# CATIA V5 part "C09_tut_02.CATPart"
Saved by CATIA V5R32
Part number: Part1
Bounding box of the stored display mesh (mm): x -258 to 0, y -74.587 to 74.587, z -81.796 to 81.796
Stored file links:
  D:\PROJECTS\Project 2022\CATIA V5 6R 2022\Resources\Tutorial Files\c09_catia_v5_6r2022_tut\C09_tut_02.CATPart
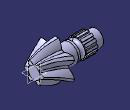
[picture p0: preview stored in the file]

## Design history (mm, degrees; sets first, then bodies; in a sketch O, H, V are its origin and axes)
Body1 (main body)
  Sketch1 on zx-plane, origin (0, 0, 0), H (-1, 0, 0), V (0, 0, 1)
    line L1 (0, 0) -> (258, 0)
    line L2 (258, 0) -> (258, -32.5)
    line L3 (0, 0) -> (0, -25)
    line L4 (0, -25) -> (95, -50)
    point P4 (95, -50)
    point P5 (95, -50)
    line L5 (95, -50) -> (95, -45)
    line L6 (95, -45) -> (100, -45)
    line L7 (100, -45) -> (100, -39)
    line L8 (100, -39) -> (146, -39)
    line L9 (258, -32.5) -> (226, -32.5)
    line L10 (226, -32.5) -> (226, -36)
    line L11 (226, -36) -> (178, -36)
    arc A1 centre (167, -36) radius 11 from (178, -36) to (156, -36) ccw
    point P13 (167, -36)
    line L12 (146, -39) -> (146, -38)
    line L13 (146, -38) -> (156, -38)
    line L14 (156, -38) -> (156, -36)
    point P16 (156, -36)
    point P17 (156, -36)
    axis line L15 (258, 0) -> (-34.5416, 0)
    length L1 = 258
    length L2 = 32.5
    length L3 = 25
    distance P4 L3 = 95
    length L6 = 5
    distance L6 L1 = 45
    length L9 = 32
    radius A1 = 11
    length L13 = 10
    length L14 = 2
    distance L13 L1 = 38
    length L11 = 48
    distance L8 L1 = 39
    distance P4 L1 = 50
    distance L11 L1 = 36
    horizontal: L1 H, L6 H, L8 H, L9 H, L11 H, L13 H, L15 H
    vertical: L2 V, L3 V, L5 V, L7 V, L10 V, L12 V, L14 V
    coincidence: P5 P4, P13 L11, P16 P17
  Shaft1: profile Sketch1, axis Sketch1.L15, angle 360
  Sketch2 on face of Shaft1 from Sketch1.L10, origin (-226, 0, 0), H (0, -1, 0), V (0, 0, 1)
    line L1 (-5, 40.6511) -> (5, 40.6511)
    line L2 (5, 40.6511) -> (5, 35.6511)
    line L3 (-5, 35.6511) -> (-5, 40.6511)
    point P3 (5, 35.6511)
    point P4 (-5, 35.6511)
    reference projected circle E1 centre (0, 0) radius 36 from edge [face of Shaft1 from Sketch1.L10 | face of Shaft1 from Sketch1.L11]
    reference projected circle E2 centre (0, 0) radius 36 from edge [face of Shaft1 from Sketch1.L10 | face of Shaft1 from Sketch1.L11]
    point P5 (0, 35.9986)
    point P6 (12.0414, 33.9264)
    arc A1 centre (0, 0) radius 36 from (5, 35.6511) to (-5, 35.6511) ccw
    length L3 = 5
    length L1 = 10
    distance L2 V = 5
    horizontal: L1 H
    vertical: L2 V, L3 V
    coincidence: P3 E1, P4 E2, P5 V
  Pad1: profile Sketch2, direction (1, 0, 0), length 48
  CircPattern1: of Pad1, instances 13, angular step 27.6923 {= 360.0*1 deg/CircPattern1.AngularNumber}, axis from face of Shaft1 from Sketch1.L9
  Plane1: type Offset, RefPlane face of Shaft1 from Sketch1.L2, Offset 163
  Sketch3 on Plane1, origin (-95, 0, 0), H (0, 1, 0), V (0, 0, 1)
    projected circle E1 centre (0, 0) radius 50 from edge [face of Shaft1 from Sketch1.L5 | face of Shaft1 from Sketch1.L4]
    projected arc E2 centre (0, 0) radius 50 from (20, 45.8258) to (-20, 45.8258) ccw from edge [face of Shaft1 from Sketch1.L5 | face of Shaft1 from Sketch1.L4]
    arc A1 centre (44.9551, 43.4104) radius 65 from (-20, 45.8258) to (-7.5, 81.7961) cw
    point P2 (-20, 45.8258)
    point P3 (-7.5, 81.7961)
    point P4 (20, 45.8258)
    point P5 (7.5, 81.7961)
    arc A2 centre (-44.9551, 43.4104) radius 65 from (20, 45.8258) to (7.5, 81.7961) ccw
    line L1 (-7.5, 81.7961) -> (7.5, 81.7961)
    radius A1 = 65
    length L1 = 15
    distance P2 P4 = 40
    coincidence: P2 E1
    symmetry: P2 P4 V, P3 P5 V, A1 A2 V
    horizontal: L1 H
  Plane2: type Offset, RefPlane face of Shaft1 from Sketch1.L2, Offset 210.5
  Sketch4 on Plane2, origin (-47.5, 0, 0), H (0, 1, 0), V (0, 0, 1)
    arc A1 centre (0, 0) radius 37.5 from (5.5935, 37.0805) to (-23.3843, 29.3159) ccw
    point P1 (5.5935, 37.0805)
    point P2 (-23.3843, 29.3159)
    arc A2 centre (-40.9945, 22.7216) radius 48.7506 from (5.5935, 37.0805) to (-10.4445, 60.7126) ccw
    point P3 (-10.4445, 60.7126)
    line L1 (-10.4445, 60.7126) -> (-21.3111, 57.8008)
    point P4 (-21.3111, 57.8008)
    arc A3 centre (24.1415, 40.1748) radius 48.7506 from (-21.3111, 57.8008) to (-23.3843, 29.3159) ccw
    reference projected circle E1 centre (0, 0) radius 25 from edge [face of Shaft1 from Sketch1.L4 | face of Shaft1 from Sketch1.L3]
    length L1 = 11.25
    radius A3 = 48.7506
    radius A1 = 37.5
    angle L1 H = 15
    radius A2 = 48.7506
    distance P1 V = 5.5935
    distance P2 V = 23.3843
    distance P3 V = 10.4445
    distance P4 H = 57.8008
    concentricity: A1 E1
  Sketch5 on face of Shaft1 from Sketch1.L3, origin (0, 0, 0), H (0, 1, 0), V (0, 0, 1)
    arc A1 centre (0, 0) radius 25 from (-2.7962, 24.8431) to (-20.1167, 14.8431) ccw
    arc A2 centre (-30.319, 7.5582) radius 32.5004 from (-2.7962, 24.8431) to (-17.2014, 37.2937) ccw
    line L1 (-17.2014, 37.2937) -> (-23.6966, 33.5437)
    arc A3 centre (8.6139, 30.0361) radius 32.5004 from (-23.6966, 33.5437) to (-20.1167, 14.8431) ccw
  Loft1: solid, Sections (Sketch3; Sketch4; Sketch5)
  CircPattern2: of Loft1, instances 6, angular step 60 {= 360.0*1 deg/CircPattern2.AngularNumber}, axis from face of Shaft1 from Sketch1.L4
